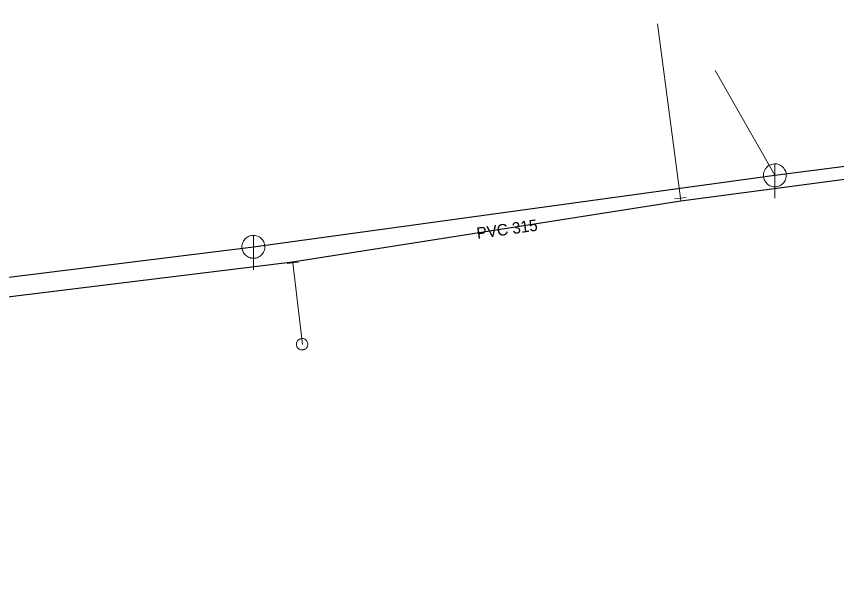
# Model space of a CAD drawing. Extents: x -807203 to -805207, y -993656 to -992505.
# Drawn here: x -806854.3 to -806782.7, y -993027.3 to -992977.1 of the extents above; entities that cross this region are included whole.
import ezdxf

# ---------------------------------------------------------------- set-up
doc = ezdxf.new("R2010")
doc.units = 0
doc.header["$LTSCALE"] = 0.4
for name, color, linetype, lineweight in [('1', 7, 'Continuous', 13), ('11', 7, 'Continuous', 13), ('13', 7, 'Continuous', 13), ('14', 7, 'Continuous', 25), ('17', 7, 'Continuous', 25), ('22', 7, 'Continuous', 13), ('23', 7, 'Continuous', 13), ('34', 7, 'Continuous', 13)]:
    doc.layers.add(name, color=color, linetype=linetype, lineweight=lineweight)

msp = doc.modelspace()

# ---------------------------------------------------------------- linework, layer by layer
at = {"layer": '11'}
msp.add_line((-806793.27, -992981.84), (-806788.059, -992990.989), dxfattribs=at)
at = {"layer": '13'}
for p in [(-806798.309, -992977.76), (-806796.28, -992993.219)]:
    msp.add_line(p, (-806796.308, -992992.991), dxfattribs=at)
msp.add_lwpolyline([(-806830.19, -992998.53), (-806830.177, -992998.62), (-806829.332, -993005.753)], dxfattribs=at)
at = {"layer": '14'}
msp.add_lwpolyline([(-807063.899, -993027.32), (-807029.679, -993022.599), (-806980.12, -993015.92), (-806932.19, -993009.809), (-806883.41, -993003.39), (-806833.609, -992997.23), (-806788.059, -992990.989), (-806765.85, -992988.129), (-806739.039, -992984.52), (-806699.85, -992977.12)], dxfattribs=at)
at = {"layer": '17'}
msp.add_lwpolyline([(-806889.945, -993005.863), (-806830.19, -992998.53), (-806796.28, -992993.219), (-806733.749, -992984.949)], dxfattribs=at)
at = {"layer": '22'}
for p, q in [((-806788.059, -992992.989), (-806788.058, -992989.989)), ((-806833.609, -992999.23), (-806833.608, -992996.23))]:
    msp.add_line(p, q, dxfattribs=at)
for points in [[(-806787.059, -992990.989), (-806787.064, -992990.88), (-806787.082, -992990.772), (-806787.112, -992990.666), (-806787.152, -992990.565), (-806787.204, -992990.468), (-806787.266, -992990.378), (-806787.338, -992990.295), (-806787.418, -992990.221), (-806787.506, -992990.155), (-806787.6, -992990.1), (-806787.7, -992990.055), (-806787.805, -992990.022), (-806787.912, -992990), (-806788.021, -992989.99), (-806788.131, -992989.992), (-806788.239, -992990.006), (-806788.346, -992990.031), (-806788.449, -992990.068), (-806788.547, -992990.117), (-806788.639, -992990.175), (-806788.725, -992990.244), (-806788.802, -992990.321), (-806788.871, -992990.407), (-806788.93, -992990.499), (-806788.978, -992990.597), (-806789.015, -992990.7), (-806789.041, -992990.807), (-806789.055, -992990.915), (-806789.058, -992991.025), (-806789.048, -992991.134), (-806789.027, -992991.241), (-806788.993, -992991.345), (-806788.949, -992991.445), (-806788.894, -992991.54), (-806788.828, -992991.628), (-806788.754, -992991.708), (-806788.671, -992991.78), (-806788.581, -992991.842), (-806788.485, -992991.894), (-806788.383, -992991.935), (-806788.278, -992991.965), (-806788.17, -992991.983), (-806788.06, -992991.989), (-806787.951, -992991.983), (-806787.843, -992991.965), (-806787.738, -992991.936), (-806787.636, -992991.895), (-806787.539, -992991.843), (-806787.449, -992991.781), (-806787.366, -992991.71), (-806787.291, -992991.63), (-806787.226, -992991.542), (-806787.17, -992991.448), (-806787.126, -992991.348), (-806787.092, -992991.244), (-806787.07, -992991.136), (-806787.06, -992991.027)], [(-806832.609, -992997.23), (-806832.614, -992997.121), (-806832.632, -992997.013), (-806832.662, -992996.907), (-806832.702, -992996.806), (-806832.754, -992996.709), (-806832.816, -992996.619), (-806832.888, -992996.536), (-806832.968, -992996.462), (-806833.056, -992996.396), (-806833.15, -992996.341), (-806833.25, -992996.296), (-806833.355, -992996.263), (-806833.462, -992996.241), (-806833.571, -992996.231), (-806833.681, -992996.233), (-806833.789, -992996.247), (-806833.896, -992996.272), (-806833.999, -992996.309), (-806834.097, -992996.358), (-806834.189, -992996.416), (-806834.275, -992996.485), (-806834.352, -992996.562), (-806834.421, -992996.648), (-806834.48, -992996.74), (-806834.528, -992996.838), (-806834.565, -992996.941), (-806834.591, -992997.048), (-806834.605, -992997.156), (-806834.608, -992997.266), (-806834.598, -992997.375), (-806834.577, -992997.482), (-806834.543, -992997.586), (-806834.499, -992997.686), (-806834.444, -992997.781), (-806834.378, -992997.869), (-806834.304, -992997.949), (-806834.221, -992998.021), (-806834.131, -992998.083), (-806834.035, -992998.135), (-806833.933, -992998.176), (-806833.828, -992998.206), (-806833.72, -992998.224), (-806833.61, -992998.23), (-806833.501, -992998.224), (-806833.393, -992998.206), (-806833.288, -992998.177), (-806833.186, -992998.136), (-806833.089, -992998.084), (-806832.999, -992998.022), (-806832.916, -992997.951), (-806832.841, -992997.871), (-806832.776, -992997.783), (-806832.72, -992997.689), (-806832.676, -992997.589), (-806832.642, -992997.485), (-806832.62, -992997.377), (-806832.61, -992997.268)]]:
    msp.add_lwpolyline(points, close=True, dxfattribs=at)
at = {"layer": '23'}
for points in [[(-806828.906, -993005.517), (-806828.929, -993005.472), (-806828.959, -993005.428), (-806828.995, -993005.388), (-806829.032, -993005.352), (-806829.074, -993005.32), (-806829.118, -993005.292), (-806829.165, -993005.27), (-806829.215, -993005.253), (-806829.265, -993005.241), (-806829.317, -993005.234), (-806829.369, -993005.233), (-806829.421, -993005.237), (-806829.473, -993005.246), (-806829.523, -993005.261), (-806829.572, -993005.281), (-806829.618, -993005.305), (-806829.659, -993005.335), (-806829.7, -993005.369), (-806829.737, -993005.407), (-806829.769, -993005.449), (-806829.796, -993005.493), (-806829.818, -993005.539), (-806829.836, -993005.59), (-806829.849, -993005.64), (-806829.855, -993005.693), (-806829.856, -993005.744), (-806829.852, -993005.796), (-806829.842, -993005.847), (-806829.828, -993005.898), (-806829.808, -993005.947), (-806829.783, -993005.992), (-806829.754, -993006.036), (-806829.721, -993006.076), (-806829.681, -993006.111), (-806829.641, -993006.144), (-806829.597, -993006.171), (-806829.548, -993006.194), (-806829.499, -993006.211), (-806829.448, -993006.224)], [(-806829.796, -993005.493), (-806829.818, -993005.539), (-806829.836, -993005.59), (-806829.849, -993005.64), (-806829.855, -993005.693), (-806829.856, -993005.744), (-806829.852, -993005.796), (-806829.842, -993005.847), (-806829.828, -993005.898), (-806829.808, -993005.947), (-806829.783, -993005.992), (-806829.754, -993006.036), (-806829.721, -993006.076), (-806829.681, -993006.111), (-806829.641, -993006.144), (-806829.597, -993006.171), (-806829.548, -993006.194), (-806829.499, -993006.211), (-806829.448, -993006.224), (-806829.396, -993006.229), (-806829.345, -993006.231), (-806829.293, -993006.228), (-806829.24, -993006.219), (-806829.19, -993006.204), (-806829.143, -993006.183), (-806829.097, -993006.159), (-806829.054, -993006.129), (-806829.014, -993006.094), (-806828.978, -993006.057), (-806828.946, -993006.016), (-806828.918, -993005.971), (-806828.896, -993005.924), (-806828.877, -993005.875), (-806828.865, -993005.823), (-806828.858, -993005.772), (-806828.857, -993005.72), (-806828.861, -993005.668), (-806828.871, -993005.615), (-806828.885, -993005.567), (-806828.906, -993005.517)], [(-806829.293, -993006.228), (-806829.24, -993006.219), (-806829.19, -993006.204), (-806829.143, -993006.183), (-806829.097, -993006.159), (-806829.054, -993006.129), (-806829.014, -993006.094), (-806828.978, -993006.057), (-806828.946, -993006.016), (-806828.918, -993005.971), (-806828.896, -993005.924), (-806828.877, -993005.875), (-806828.865, -993005.823), (-806828.858, -993005.772), (-806828.857, -993005.72), (-806828.861, -993005.668), (-806828.871, -993005.615), (-806828.885, -993005.567), (-806828.906, -993005.517), (-806828.929, -993005.472), (-806828.959, -993005.428), (-806828.995, -993005.388), (-806829.032, -993005.352), (-806829.074, -993005.32), (-806829.118, -993005.292), (-806829.165, -993005.27), (-806829.215, -993005.253), (-806829.265, -993005.241), (-806829.317, -993005.234), (-806829.369, -993005.233), (-806829.421, -993005.237), (-806829.473, -993005.246), (-806829.523, -993005.261), (-806829.572, -993005.281), (-806829.618, -993005.305), (-806829.659, -993005.335), (-806829.7, -993005.369), (-806829.737, -993005.407), (-806829.769, -993005.449), (-806829.796, -993005.493)], [(-806829.448, -993006.224), (-806829.396, -993006.229), (-806829.345, -993006.231), (-806829.293, -993006.228)]]:
    msp.add_lwpolyline(points, dxfattribs=at)
at = {"layer": '34'}
for p, q in [((-806795.812, -992992.925), (-806796.803, -992993.055)), ((-806830.673, -992998.679), (-806829.68, -992998.561))]:
    msp.add_line(p, q, dxfattribs=at)

# ---------------------------------------------------------------- texts
at = {"layer": '1'}
msp.add_text('PVC 315 ', height=1, rotation=8, dxfattribs=at).set_placement((-806814.032, -992996.551))

doc.saveas('drawing.dxf')
